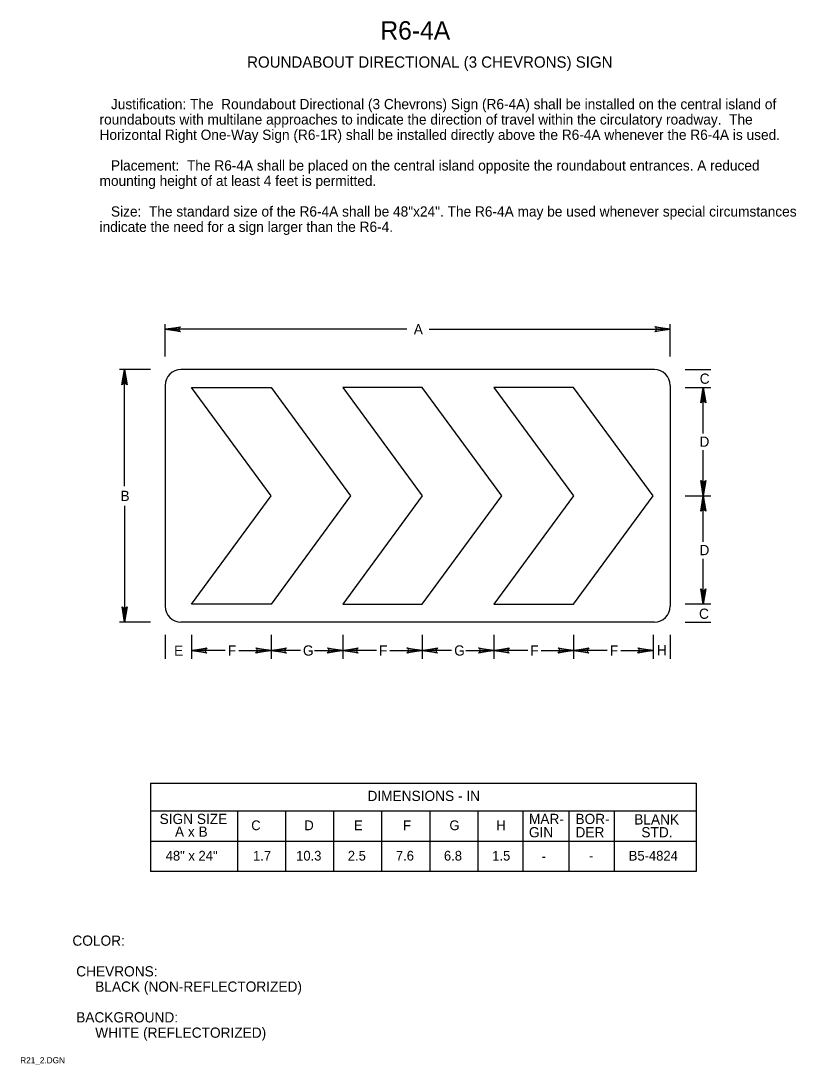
# Model space of a CAD drawing. Extents: x 0.013 to 0.202, y 0.004 to 0.259.
import ezdxf

# ---------------------------------------------------------------- set-up
doc = ezdxf.new("R2010")
doc.units = 0
for name, color, linetype in [('1', 7, 'Continuous'), ('2', 7, 'Continuous'), ('3', 7, 'Continuous')]:
    doc.layers.add(name, color=color, linetype=linetype)

# ---------------------------------------------------------------- blocks, each defined once
blk = doc.blocks.new('RARROW')
at = {"layer": '3'}
for p, q in [((-2.156, 0.285), (-2.2665, 0.384625)), ((-2.2665, 0.384625), (0, 0)), ((0, 0), (-2.2665, -0.379125)), ((-2.156, 0.285), (-2.075625, 0.12075)), ((0, 0), (-2.156, 0.285)), ((-2.14975, -0.2705), (0, 0)), ((-2.075625, 0.12075), (0, 0)), ((0, 0), (-2.074, -0.108)), ((-2.2665, -0.379125), (-2.14975, -0.2705)), ((-2.074, -0.108), (-2.14975, -0.2705))]:
    blk.add_line(p, q, dxfattribs=at)

msp = doc.modelspace()

# ---------------------------------------------------------------- linework, layer by layer
at = {"layer": '3'}
for p, q in [((0.0478, 0.17719), (0.0478, 0.18507)), ((0.10682, 0.18382), (0.0478, 0.18382)), ((0.11228, 0.18382), (0.1712, 0.18382)), ((0.1712, 0.17719), (0.1712, 0.18507)), ((0.04424, 0.17395), (0.03662, 0.17395)), ((0.03787, 0.14547), (0.03787, 0.17395)), ((0.16736, 0.17395), (0.05166, 0.17395)), ((0.17487, 0.17395), (0.18112, 0.17395)), ((0.0478, 0.17009), (0.0478, 0.1161)), ((0.07367, 0.14309), (0.05423, 0.1696)), ((0.05423, 0.1696), (0.07367, 0.1696)), ((0.17121, 0.17009), (0.17121, 0.1161)), ((0.17487, 0.1696), (0.18112, 0.1696)), ((0.17929, 0.15835), (0.17929, 0.1696)), ((0.17929, 0.14309), (0.17929, 0.15423)), ((0.05423, 0.11658), (0.07367, 0.14309)), ((0.17487, 0.14309), (0.18112, 0.14309)), ((0.17929, 0.13184), (0.17929, 0.14309)), ((0.03787, 0.14064), (0.03787, 0.1122)), ((0.17929, 0.11658), (0.17929, 0.12773)), ((0.18112, 0.11658), (0.17487, 0.11658)), ((0.04424, 0.1122), (0.03662, 0.1122)), ((0.16736, 0.11224), (0.05166, 0.11224)), ((0.17487, 0.11224), (0.18112, 0.11224)), ((0.0478, 0.1091), (0.0478, 0.10328)), ((0.05423, 0.1091), (0.05423, 0.10328)), ((0.07367, 0.1091), (0.07367, 0.10328)), ((0.09119, 0.1091), (0.09119, 0.10328)), ((0.11063, 0.1091), (0.11063, 0.10328)), ((0.12815, 0.1091), (0.12815, 0.10328)), ((0.14759, 0.1091), (0.14759, 0.10328)), ((0.16703, 0.1091), (0.16703, 0.10328)), ((0.17121, 0.1091), (0.17121, 0.10328)), ((0.06247, 0.10529), (0.05436, 0.10529)), ((0.06577, 0.10529), (0.07367, 0.10529)), ((0.08083, 0.10529), (0.0738, 0.10529)), ((0.08431, 0.10529), (0.09119, 0.10529)), ((0.09943, 0.10529), (0.09132, 0.10529)), ((0.10273, 0.10529), (0.11063, 0.10529)), ((0.11779, 0.10529), (0.11076, 0.10529)), ((0.12127, 0.10529), (0.12815, 0.10529)), ((0.13639, 0.10529), (0.12827, 0.10529)), ((0.13969, 0.10529), (0.14759, 0.10529)), ((0.15583, 0.10529), (0.14772, 0.10529)), ((0.15913, 0.10529), (0.16703, 0.10529)), ((0.04419, 0.07287), (0.17756, 0.07287)), ((0.04419, 0.07287), (0.04419, 0.05125)), ((0.17756, 0.07287), (0.17756, 0.05125)), ((0.17756, 0.066), (0.04419, 0.066)), ((0.06544, 0.066), (0.06544, 0.05125)), ((0.07719, 0.066), (0.07719, 0.05125)), ((0.08894, 0.066), (0.08894, 0.05125)), ((0.10069, 0.066), (0.10069, 0.05125)), ((0.11244, 0.066), (0.11244, 0.05125)), ((0.12419, 0.066), (0.12419, 0.05125)), ((0.12419, 0.066), (0.12419, 0.05262)), ((0.1352, 0.066), (0.1352, 0.05125)), ((0.14644, 0.066), (0.14644, 0.05125)), ((0.15756, 0.066), (0.15756, 0.05125)), ((0.17756, 0.05862), (0.04419, 0.05862)), ((0.17756, 0.05125), (0.04419, 0.05125))]:
    msp.add_line(p, q, dxfattribs=at)
msp.add_lwpolyline([(0.07367, 0.1696), (0.09311, 0.14309), (0.07367, 0.11658), (0.05423, 0.11658)], dxfattribs=at)
for points in [[(0.11063, 0.1696), (0.09119, 0.1696), (0.11063, 0.14309), (0.09119, 0.11658), (0.11063, 0.11658), (0.13007, 0.14309)], [(0.14759, 0.1696), (0.12815, 0.1696), (0.14759, 0.14309), (0.12815, 0.11658), (0.14759, 0.11658), (0.16703, 0.14309)]]:
    msp.add_lwpolyline(points, close=True, dxfattribs=at)
for centre, start, end in [((0.05166, 0.17009), 90, 180), ((0.16736, 0.17009), 0, 90), ((0.05166, 0.1161), 180, 270), ((0.16736, 0.1161), 270, 0)]:
    msp.add_arc(centre, 0.00386, start, end, dxfattribs=at)

# ---------------------------------------------------------------- block references
at = {"layer": '3', "xscale": 0.0016545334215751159, "yscale": 0.0016366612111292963}
for p, rotation in [((0.0478, 0.18382), 180), ((0.03787, 0.17395), 90), ((0.17929, 0.1696), 90), ((0.17929, 0.14309), -90), ((0.17929, 0.14309), 90), ((0.17929, 0.11658), -90), ((0.03787, 0.1122), -90), ((0.05423, 0.10529), 180), ((0.07367, 0.10529), 180), ((0.09119, 0.10529), 180), ((0.11063, 0.10529), 180), ((0.12815, 0.10529), 180), ((0.14759, 0.10529), 180)]:
    msp.add_blockref('RARROW', p, dxfattribs=dict(at, rotation=rotation))
for p in [(0.1712, 0.18382), (0.07367, 0.10529), (0.09119, 0.10529), (0.11063, 0.10529), (0.12815, 0.10529), (0.14759, 0.10529), (0.16703, 0.10529)]:
    msp.add_blockref('RARROW', p, dxfattribs=at)

# ---------------------------------------------------------------- texts
at = {"layer": '1'}
for s, height, p in [('R6-4A', 0.0045, (0.10039, 0.25462)), ('ROUNDABOUT DIRECTIONAL (3 CHEVRONS) SIGN', 0.0027503, (0.06782, 0.24775)), ('COLOR:', 0.0025, (0.02513, 0.03312)), (' CHEVRONS:', 0.0025, (0.02513, 0.02562)), ('      BLACK (NON-REFLECTORIZED)', 0.0024998, (0.02513, 0.02188)), (' BACKGROUND:', 0.0024998, (0.02513, 0.01438)), ('      WHITE (REFLECTORIZED)', 0.0024998, (0.02513, 0.01063)), ('R21_2.DGN', 0.0015, (0.01238, 0.00438))]:
    msp.add_text(s, height=height, dxfattribs=at).set_placement(p)
at = {"layer": '2'}
for s, height, p in [('   Justification: The  Roundabout Directional (3 Chevrons) Sign (R6-4A) shall be installed on the central island of', 0.00249975, (0.03176, 0.23761)), ('roundabouts with multilane approaches to indicate the direction of travel within the circulatory roadway.  The ', 0.00249975, (0.03176, 0.23386)), ('Horizontal Right One-Way Sign (R6-1R) shall be installed directly above the R6-4A whenever the R6-4A is used.', 0.00249975, (0.03176, 0.23011)), ('   Placement:  The R6-4A shall be placed on the central island opposite the roundabout entrances. A reduced', 0.00249975, (0.03176, 0.22261)), ('mounting height of at least 4 feet is permitted.', 0.0024998, (0.03176, 0.21886)), ('   Size:  The standard size of the R6-4A shall be 48"x24". The R6-4A may be used whenever special circumstances ', 0.00249975, (0.03176, 0.21136)), ('indicate the need for a sign larger than the R6-4.', 0.0024998, (0.03176, 0.20761))]:
    msp.add_text(s, height=height, dxfattribs=at).set_placement(p)
at = {"layer": '3'}
for s, height, p in [('A', 0.0025, (0.10855, 0.18257)), ('C', 0.0025, (0.17843, 0.17049)), ('D', 0.0025, (0.17836, 0.15509)), ('B', 0.0025, (0.03687, 0.14184)), ('D', 0.0025, (0.17836, 0.12859)), ('C', 0.0025, (0.17826, 0.11303)), ('E', 0.0025, (0.04998, 0.10401)), ('F', 0.0025, (0.0631, 0.10404)), ('G', 0.0025, (0.08146, 0.10404)), ('F', 0.0025, (0.10006, 0.10404)), ('G', 0.0025, (0.11842, 0.10404)), ('F', 0.0025, (0.13702, 0.10404)), ('F', 0.0025, (0.15646, 0.10404)), ('H', 0.0025, (0.16798, 0.1041)), ('DIMENSIONS - IN', 0.0024998, (0.09724, 0.0685)), ('SIGN SIZE', 0.0025, (0.04644, 0.06287)), ('MAR-', 0.0025, (0.13669, 0.06287)), ('BOR-', 0.0025, (0.14806, 0.06287)), ('BLANK', 0.0025, (0.16242, 0.06275)), ('A x B', 0.0025, (0.05019, 0.05975)), (' C', 0.002375, (0.06795, 0.06137)), ('D', 0.00238, (0.08181, 0.06137)), ('E', 0.00238, (0.09394, 0.06137)), ('F', 0.00238, (0.10594, 0.06137)), ('G', 0.00238, (0.11727, 0.06137)), ('H', 0.00238, (0.12872, 0.06137)), ('GIN', 0.0025, (0.13669, 0.05962)), ('DER', 0.0025, (0.14806, 0.05962)), ('STD.', 0.0025, (0.16417, 0.05962)), ('48" x 24"', 0.002375, (0.04793, 0.05394)), ('1.7', 0.002375, (0.06927, 0.05394)), ('10.3', 0.002375, (0.0798, 0.05394)), ('2.5', 0.002375, (0.09243, 0.05394)), ('7.6', 0.002375, (0.10418, 0.05394)), ('6.8', 0.002375, (0.11592, 0.05394)), ('1.5', 0.002375, (0.12772, 0.05394)), ('B5-4824', 0.002375, (0.16108, 0.05394)), ('-', 0.00238, (0.13979, 0.05381)), ('-', 0.00238, (0.15138, 0.05394))]:
    msp.add_text(s, height=height, dxfattribs=at).set_placement(p)

doc.saveas('drawing.dxf')
